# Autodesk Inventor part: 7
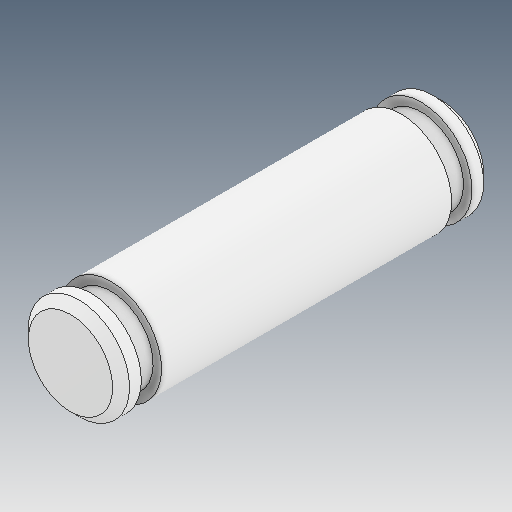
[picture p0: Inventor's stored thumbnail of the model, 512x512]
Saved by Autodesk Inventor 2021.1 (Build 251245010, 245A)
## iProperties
Created: 2021-06
Part Number: 7
Material: Ogólny
Document SubType Name: Modeling
Designer: user
Density: 1 g/cm^3
Appearance: Domyślna
Author: user
Revision Number: ÈÎºÎ
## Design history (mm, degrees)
feature "ÊäÈë1"
node "Bryła1"
